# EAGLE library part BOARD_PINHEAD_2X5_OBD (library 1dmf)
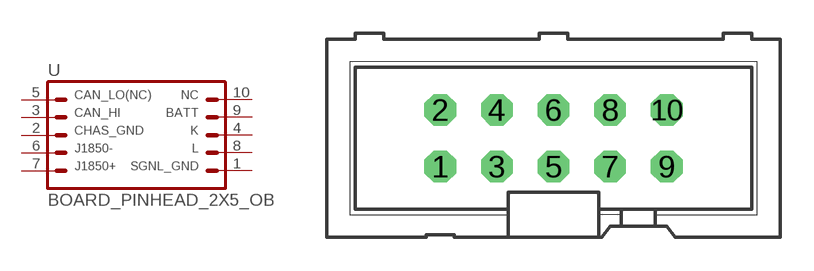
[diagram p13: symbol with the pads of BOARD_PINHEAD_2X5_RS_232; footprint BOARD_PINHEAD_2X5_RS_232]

Designator prefix -

## BOARD_PINHEAD_2X5_OBD  [BOARD_PINHEAD_2X5_RS_232]
1  SGNL_GND  pas
2  CHAS_GND  pas
3  CAN_HI  pas
4  K  pas
5  CAN_LO  pas
6  J1850-  pas
7  J1850+  pas
8  L  pas
9  BATT  pas
10  10  pas

## Footprint BOARD_PINHEAD_2X5_RS_232 (pad centres in mm)
drill 0.914 octagon: 1 -5.08,-1.27; 2 -5.08,1.27; 3 -2.54,-1.27; 4 -2.54,1.27; 5 0,-1.27; 6 0,1.27; 7 2.54,-1.27; 8 2.54,1.27; 9 5.08,-1.27; 10 5.08,1.27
